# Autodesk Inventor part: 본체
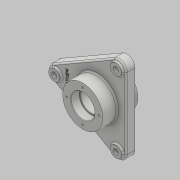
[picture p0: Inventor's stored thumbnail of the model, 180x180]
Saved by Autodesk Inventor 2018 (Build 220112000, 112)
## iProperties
Created: 2023-04
Part Number: 본체
Material: 일반
Document SubType Name: Modeling
Designer: home
Density: 1 g/cm^3
Appearance: 기본값
Author: home
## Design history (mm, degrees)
sketch "스케치1"
  geometry: L1 (82, 0)-(0, 0); L2 (0, 0)-(-40.998, 71.01); L3 (0, 0)-(-40.998, -71.018); L4 (90, 13.857)-(-32.998, 84.866); L5 (-56.998, 71.01)-(-56.998, -71.018); L6 (90, -13.856)-(-32.997, -84.874); A1 r 16 centre (82, 0) between (90, -13.856) and (90, 13.857); A2 r 16 centre (-40.998, 71.01) between (-32.998, 84.866) and (-56.998, 71.01); A3 r 16 centre (-40.998, -71.018) between (-56.998, -71.018) and (-32.997, -84.874); 1 further point
  constraints: 12 end point, 6 point on circle, 6 tangent, 3 centre point, 3 coincident, 1 horizontal, 1 vertical
  dimensions: "d3" = 16 radius of A1; "d4" = 16 radius of A2; "d5" = 16 radius of A3
extrude "돌출1" new body sketch "스케치1" distance "d6" = 18; taper "d7" = 0 deg
sketch "스케치2"
  geometry: C1 r 40 at (0, 0); 1 further point
  constraints: 1 centre point
  dimensions: "d9" = 80 diameter of C1
extrude "돌출2" join sketch "스케치2" distance "d10" = 23; taper "d12" = 0 deg; dims "d11" = 47, "d13" = 0
sketch "스케치3"
  geometry: C1 r 45 at (0, 0); 1 further point
  constraints: 1 centre point, 1 coincident
  dimensions: "d14" = 90 diameter of C1
extrude "돌출3" join sketch "스케치3" distance "d15" = 5; taper "d16" = 0 deg
fillet "모깎기1" dims "d17" = 3
sketch "스케치4"
  geometry: C1 r 11 at (40.998, 71.01); C2 r 11 at (40.998, -71.018); C3 r 11 at (-82, 0); A1 r 16 centre (40.998, 71.01) between (56.998, 71.01) and (32.998, 84.866) reference; A2 r 16 centre (40.998, -71.018) between (32.997, -84.874) and (56.998, -71.018) reference; A3 r 16 centre (-82, 0) between (-90, 13.857) and (-90, -13.856) reference; 1 further point
  constraints: 3 centre point, 3 coincident
  dimensions: "d18" = 22 diameter of C1; "d19" = 22 diameter of C2; "d20" = 22 diameter of C3
extrude "돌출4" join sketch "스케치4" distance "d21" = 4; taper "d22" = 0 deg
fillet "모깎기2" dims "d23" = 3
hole "구멍1" diameter "d26" = 11; stored, may be unused: countersink angle "d30" = 90 deg, drill point angle "d32" = 118 deg; dims "d24" = 10, "d25" = 10, "d27" = 6, "d28" = 4, "d29" = 2, "d31" = 30
hole "구멍2" diameter "d35" = 11; stored, may be unused: countersink angle "d39" = 90 deg, drill point angle "d41" = 118 deg; dims "d33" = 10, "d34" = 10, "d36" = 6, "d37" = 4, "d38" = 2, "d40" = 30
hole "구멍3" diameter "d44" = 11; stored, may be unused: countersink angle "d48" = 90 deg, drill point angle "d50" = 118 deg; dims "d42" = 10, "d43" = 10, "d45" = 6, "d46" = 4, "d47" = 2, "d49" = 30
hole "구멍4" diameter "d53" = 42; stored, may be unused: countersink angle "d57" = 90 deg, drill point angle "d59" = 118 deg; dims "d51" = 10, "d52" = 10, "d54" = 6, "d55" = 47, "d56" = 17, "d58" = 80
hole "구멍5" diameter "d62" = 42; stored, may be unused: countersink angle "d66" = 90 deg, drill point angle "d68" = 118 deg; dims "d60" = 10, "d61" = 10, "d63" = 6, "d64" = 47, "d65" = 17, "d67" = 80
fillet "모깎기3" dims "d69" = 0.6
chamfer "모따기1" distance "d70" = 1; stored, may be unused: second distance "d71" = 2, angle "d72" = 45 deg
sketch "스케치5" dims "d73" = 64
  geometry: 3 further points
  constraints: 1 coincident, 1 horizontal alignment, 2 other
hole "구멍6" sketch "스케치5" at (32, 0) diameter "d74" = 3.242; stored, may be unused: countersink angle "d78" = 90 deg, drill point angle "d80" = 118 deg; dims "d75" = 8, "d76" = 47, "d77" = 17, "d79" = 10
sketch "스케치6"
  geometry: C1 r 32 at (0, 0); C2 r 1.621 at (32, 0) reference; 2 further points
  constraints: 2 coincident, 1 centre point
  dimensions: "d84" = 64 diameter of C1
hole "구멍7" sketch "스케치6" at (32, 0) diameter "d85" = 3.242; stored, may be unused: countersink angle "d89" = 90 deg, drill point angle "d91" = 118 deg; dims "d86" = 8, "d87" = 47, "d88" = 17, "d90" = 10
sketch "스케치7"
  geometry: 2 further points
  constraints: 1 horizontal alignment, 1 other
  dimensions: "d95" = 60 distance of point (0, 0) point (-60, 0)
feature "엠보싱1" sketch "스케치7" dims "d3" = 16, "d4" = 16, "d5" = 16, "d96" = 0.5, "d97" = 0
node "솔리드1"
pattern_circular "원형 패턴1" dims angle "d82" = 360 deg
pattern_circular "원형 패턴2" dims angle "d93" = 360 deg
